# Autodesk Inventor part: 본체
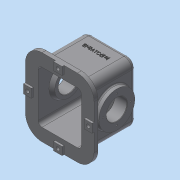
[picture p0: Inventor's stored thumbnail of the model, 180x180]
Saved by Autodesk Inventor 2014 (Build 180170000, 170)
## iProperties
Created: 2014-11
Part Number: 본체
Material: 일반
Document SubType Name: Modeling
Designer: user
Density: 1 g/cm^3
Appearance: 기본값
Author: user
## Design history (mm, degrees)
sketch "스케치1"
  geometry: L1 (-65, 59)-(65, 59); L2 (65, 59)-(65, -59); L3 (65, -59)-(-65, -59); L4 (-65, -59)-(-65, 59); 3 further points
  constraints: 8 end point, 2 midpoint, 2 parallel, 1 horizontal, 1 horizontal alignment, 1 perpendicular, 1 vertical alignment
  dimensions: "d0" = 130 distance of L1.start L1.end; "d1" = 118 distance of L1.end L2.end
extrude "돌출1" new body sketch "스케치1" distance "d2" = 152; taper "d3" = 0 deg
sketch "스케치2"
  geometry: L1 (130, 0)-(0, 0) reference; L2 (130, 0)-(130, 152) reference; L3 (0, 152)-(130, 152) reference; L4 (0, 0)-(0, 152) reference; L5 (152, -22)-(-22, -22); L6 (-22, -22)-(-22, 174); L7 (-22, 174)-(152, 174); L8 (152, 174)-(152, -22); 5 further points
  constraints: 8 end point, 4 midpoint, 2 parallel, 1 horizontal, 1 horizontal alignment, 1 perpendicular, 1 vertical alignment
  dimensions: "d4" = 174 distance of L5.start L5.end; "d5" = 196 distance of L5.end L6.end
extrude "돌출2" join sketch "스케치2" distance "d6" = 10; taper "d7" = 0 deg
sketch "스케치3"
  geometry: L1 (-22, -22)-(152, -22) reference; L2 (152, -22)-(152, 174) reference; L3 (152, 174)-(-22, 174) reference; L4 (-22, 174)-(-22, -22) reference; L5 (-22, 87)-(-2, 87); L6 (-2, 87)-(-2, 65); L7 (-2, 65)-(-22, 65); L8 (-22, 65)-(-22, 87); L9 (54, 174)-(76, 174); L10 (76, 174)-(76, 154); L11 (76, 154)-(54, 154); L12 (54, 154)-(54, 174); L13 (152, 87)-(132, 87); L14 (132, 87)-(132, 65); L15 (132, 65)-(152, 65); L16 (152, 65)-(152, 87); L17 (54, -22)-(76, -22); L18 (76, -22)-(76, -2); L19 (76, -2)-(54, -2); L20 (54, -2)-(54, -22); 1 further point
  constraints: 32 end point, 8 parallel, 4 horizontal, 4 perpendicular, 4 point on line
  dimensions: "d8" = 20 distance of L17.end L18.end; "d9" = 22 distance of L18.end L19.end; "d10" = 22 distance of L15.end L13.start; "d11" = 20 distance of L13.start L13.end; "d12" = 20 distance of L11.end L9.start; "d13" = 22 distance of L9.start L9.end; "d14" = 22 distance of L7.end L5.start; "d15" = 20 distance of L5.start L5.end; "d16" = 87 distance of L1.start L7.end; "d17" = 87 distance of L15.end L1.end; "d18" = 76 distance of L1.start L17.start; "d19" = 76 distance of L9.start L3.end
extrude "돌출3" join sketch "스케치3" distance "d20" = 5; taper "d21" = 0 deg
sketch "스케치4"
  geometry: L1 (54, 22)-(54, 2) reference; L2 (76, 2)-(76, 22) reference; L3 (152, -65)-(132, -65) reference; L4 (132, -87)-(152, -87) reference; L5 (76, -174)-(76, -154) reference; L6 (54, -154)-(54, -174) reference; L7 (-22, -87)-(-2, -87) reference; L8 (-2, -65)-(-22, -65) reference; L9 (152, 22)-(-22, 22) reference; L10 (-22, 22)-(-22, -174) reference; L11 (-22, -174)-(152, -174) reference; L12 (152, -174)-(152, 22) reference; L13 (0, 0)-(0, -152) reference; L14 (130, 0)-(0, 0) reference; L15 (130, 0)-(130, -152) reference; L16 (0, -152)-(130, -152) reference; C1 r 7 at (65, 12); C2 r 7 at (142, -76); C3 r 7 at (65, -164); C4 r 7 at (-12, -76); 9 further points
  constraints: 8 midpoint, 4 centre point, 4 horizontal alignment, 4 vertical alignment, 3 equal radius
  dimensions: "d22" = 14 diameter of C4
extrude "돌출4" cut sketch "스케치4" distance "d23" = 8.6; taper "d24" = 0 deg
sketch "스케치5"
  geometry: C1 r 7 at (0, 0) reference; C2 r 4.5 at (0, 0); 1 further point
  constraints: 1 centre point, 1 coincident
  dimensions: "d25" = 9 diameter of C2
extrude "돌출5" cut sketch "스케치5" stored distance "d26" = 8.6; taper "d27" = 0 deg
sketch "스케치6"
  geometry: C1 r 7 at (0, 0) reference; C2 r 4.5 at (0, 0); 1 further point
  constraints: 1 centre point, 1 coincident
  dimensions: "d28" = 9 diameter of C2
extrude "돌출6" cut sketch "스케치6" stored distance "d29" = 8.6; taper "d30" = 0 deg
sketch "스케치7"
  geometry: C1 r 7 at (0, 0) reference; C2 r 4.5 at (0, 0); 1 further point
  constraints: 1 centre point, 1 coincident
  dimensions: "d31" = 9 diameter of C2
extrude "돌출7" cut sketch "스케치7" stored distance "d32" = 8.6; taper "d33" = 0 deg
sketch "스케치8"
  geometry: C1 r 7 at (0, 0) reference; C2 r 4.5 at (0, 0); 1 further point
  constraints: 1 centre point, 1 coincident
  dimensions: "d34" = 9 diameter of C2
extrude "돌출8" cut sketch "스케치8" stored distance "d35" = 8.6; taper "d36" = 0 deg
sketch "스케치9"
  geometry: L1 (0, -118)-(0, 0) reference; L2 (0, -118)-(152, -118) reference; L3 (152, 0)-(152, -118) reference; L4 (0, 0)-(152, 0) reference; L5 (-2, -133)-(-22, -133) reference; L6 (65, -128)-(-22, -128) reference; L7 (-22, -118)-(-22, -128) reference; C1 r 45.5 at (76, -60); 2 further points
  constraints: 1 centre point, 1 midpoint, 1 vertical alignment
  dimensions: "d37" = 68 distance from line of C1.centre L6; "d38" = 91 diameter of C1
extrude "돌출9" join sketch "스케치9" distance "d39" = 12; taper "d40" = 0 deg
sketch "스케치10"
  geometry: C1 r 45.5 at (0, 0) reference; C2 r 26 at (0, 0); 1 further point
  constraints: 1 centre point, 1 coincident
  dimensions: "d41" = 52 diameter of C2
extrude "돌출10" cut sketch "스케치10" distance "d42" = 32; taper "d43" = 0 deg
node "작업 평면1"
sketch "스케치13"
  geometry: L1 (65, 59)-(-65, 59) reference; L2 (-65, 59)-(-65, -59) reference; L3 (-65, -59)-(65, -59) reference; L4 (65, -59)-(65, 59) reference; L5 (-11, -69)-(-87, -69) reference; 3 further points
  constraints: 1 midpoint, 1 vertical alignment, 1 other
  dimensions: "d57" = 92 distance from line of L5 point (0, 23)
feature "엠보싱1" sketch "스케치13" dims "d58" = 1, "d59" = 0
node "작업 평면2"
sketch "스케치15"
  geometry: L1 (0, 0)-(62, 0) reference; L2 (62, 86)-(62, 0) reference; L3 (0, 86)-(62, 86) reference; L4 (0, 0)-(0, 86) reference; C1 r 31 at (31, 86); 1 further point
  constraints: 1 centre point, 1 midpoint
  dimensions: "d68" = 62 diameter of C1
extrude "돌출13" join sketch "스케치15" stored distance "d69" = 30; taper "d70" = 0 deg
sketch "스케치16"
  geometry: C1 r 31 at (0, 0) reference; C2 r 21 at (0, 0); 1 further point
  constraints: 1 centre point, 1 coincident
  dimensions: "d71" = 42 diameter of C2
extrude "돌출14" cut sketch "스케치16" distance "d72" = 25; taper "d73" = 0 deg
sketch "스케치17"
  geometry: C1 r 21 at (0, 0) reference; C2 r 15 at (0, 0); 1 further point
  constraints: 1 centre point, 1 coincident
  dimensions: "d74" = 30 diameter of C2
extrude "돌출15" cut sketch "스케치17" stored distance "d75" = 25; taper "d76" = 0 deg
sketch "스케치18"
  geometry: L1 (152, 22)-(-22, 22) reference; L2 (-22, 22)-(-22, -174) reference; L3 (-22, -174)-(152, -174) reference; L4 (152, -174)-(152, 22) reference; L5 (0, 0)-(0, -152) reference; L6 (130, 0)-(0, 0) reference; L7 (130, 0)-(130, -152) reference; L8 (0, -152)-(130, -152) reference; C1 r 7 at (65, -164) reference; C2 r 7 at (65, 12) reference; C3 r 7 at (142, -76) reference; C4 r 7 at (-12, -76) reference; 1 further point
  node "투영된 루프12"
fillet "모깎기1" dims "d77" = 0.3
sketch "스케치19"
  geometry: L1 (0, 152)-(130, 152) reference; L2 (0, 0)-(0, 152) reference; L3 (130, 0)-(0, 0) reference; L4 (130, 0)-(130, 152) reference; L5 (10, 142)-(120, 142); L6 (120, 10)-(10, 10); L7 (120, 142)-(120, 10); L8 (10, 10)-(10, 142); 1 further point
  constraints: 8 end point, 2 perpendicular, 1 parallel
  dimensions: "d78" = 10 distance between parallel lines of L1 L5; "d79" = 10 distance between parallel lines of L3 L6; "d92" = 10 distance from line of L2 L5.start; "d93" = 10 horizontal distance of L3.start L6.start
extrude "돌출16" cut sketch "스케치19" distance "d94" = 118; taper "d95" = 0 deg
node "작업 평면3"
sketch "스케치20"
  geometry: L1 (-77, 44.5)-(-77, -46.5) reference; L2 (-65, -46.5)-(-65, 44.5) reference; L3 (-65, -1)-(-45, -1); L4 (-45, -1)-(-45, 34.5); L5 (-45, 34.5)-(-65, 44.5); L6 (-65, 44.5)-(-65, -1); 1 further point
  constraints: 8 end point, 2 perpendicular, 1 collinear, 1 midpoint
  dimensions: "d97" = 20 distance of L3.start L3.end; "d98" = 35.5 distance of L3.end L4.end
revolve "회전1" sketch "스케치20" stored, may be unused: angle "d99" = 90 deg
node "작업 평면4"
sketch "스케치21"
  geometry: C1 r 26 at (0, 0) reference; C2 r 26 at (0, 0); 1 further point
  constraints: 1 centre point, 1 coincident, 1 concentric
extrude "돌출17" cut sketch "스케치21" distance "d101" = 150; taper "d102" = 0 deg
sketch "스케치22"
  geometry: C1 r 45.5 at (0, 0) reference; A1 r 35 centre (0, 0) between (0, 35) and (-35, 0); 3 further points
  constraints: 4 point on circle, 2 horizontal alignment, 2 vertical alignment, 1 centre point, 1 coincident
  dimensions: "d103" = 70 diameter of A1
hole "구멍2" sketch "스케치22" at (0, 35), (-35, 0), (0, -35), (35, 0) diameter "d104" = 3.242; stored, may be unused: countersink angle "d108" = 90 deg, drill point angle "d110" = 118 deg; dims "d105" = 13, "d106" = 4, "d107" = 2, "d109" = 16
node "작업 평면5"
chamfer "모따기1" distance "d112" = 1; stored, may be unused: second distance "d113" = 2, angle "d114" = 45 deg
chamfer "모따기2" distance "d115" = 1; stored, may be unused: second distance "d116" = 2, angle "d117" = 45 deg
fillet "모깎기2" dims "d118" = 42
fillet "모깎기3" dims "d119" = 20
fillet "모깎기4" dims "d120" = 10
fillet "모깎기5" dims "d121" = 3
fillet "모깎기6" dims "d122" = 3
fillet "모깎기7" dims "d123" = 3
fillet "모깎기8" dims "d124" = 10
node "솔리드1"
mirror "대칭1"
mirror "대칭2"
mirror "대칭3"
node "투영된 루프1"
node "투영된 루프2"
node "투영된 루프3"
node "투영된 루프4"
node "투영된 루프5"
node "투영된 루프6"
node "투영된 루프8"
node "투영된 루프9"
node "투영된 루프10"
node "투영된 루프11"
node "투영된 루프13"
node "투영된 루프14"
other parameters: "d52" = 0, "d96" = 76, "d100" = 0, "d111" = 0
